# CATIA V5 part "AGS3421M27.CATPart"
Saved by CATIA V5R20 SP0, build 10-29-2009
Part number: AGS3421M27
Definition: NONE
Nomenclature: AGS3421M27
Source: Unknown
Description: AGS3421M27
Bounding box of the stored display mesh (mm): x -30 to 50, y -21.312 to 21.312, z -17.2 to 17.2
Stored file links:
  C:\Users\Utente\Desktop\IO LAVORO\3D X SITO CF\X SITO\PLASTICA\AGS\AGS3421M27.CATPart
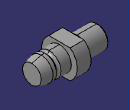
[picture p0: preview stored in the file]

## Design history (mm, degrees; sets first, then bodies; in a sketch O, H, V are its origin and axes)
Body1 "AGS3421M27" (main body)
  Solid1: solid without history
